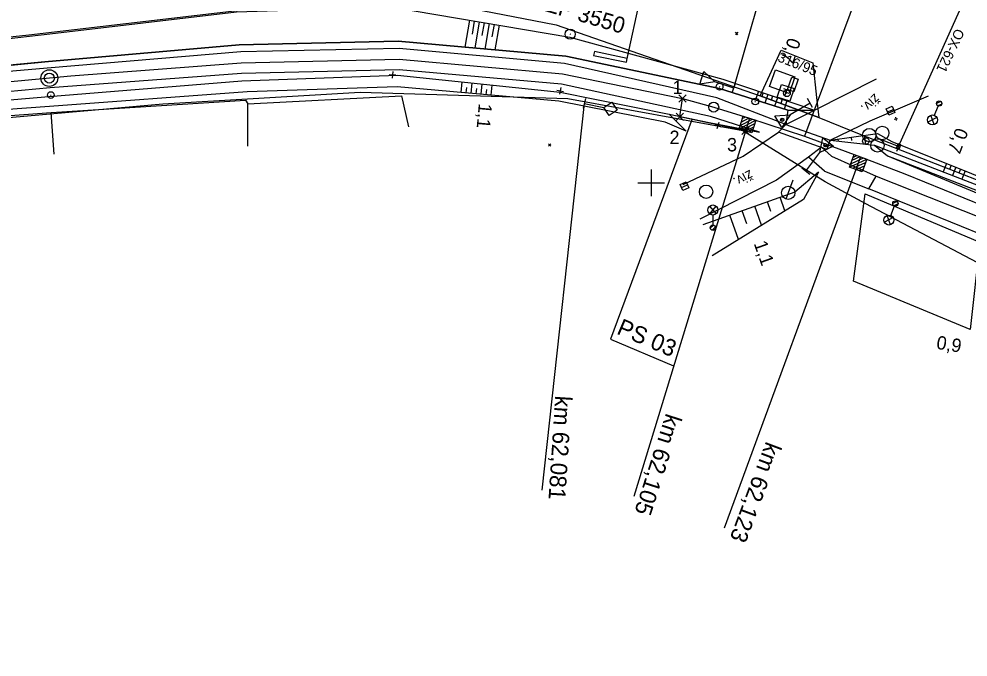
# Model space of a CAD drawing. Extents: x -805636 to -804553, y -1165340 to -1164656.
# Drawn here: x -805494.5 to -805352.6, y -1164970.9 to -1164875.5 of the extents above; entities that cross this region are included whole.
import ezdxf

# ---------------------------------------------------------------- set-up
doc = ezdxf.new("R2010")
doc.units = 0
for name, color, linetype in [('0381KM061-064P - Vrstva 1', 7, 'Continuous'), ('0381KM061-064P - Vrstva 12', 7, 'Continuous'), ('0381KM061-064P - Vrstva 16', 7, 'Continuous'), ('0381KM061-064P - Vrstva 17', 7, 'Continuous'), ('0381KM061-064P - Vrstva 23', 7, 'Continuous'), ('0381KM061-064P - Vrstva 25', 7, 'Continuous'), ('0381KM061-064P - Vrstva 27', 7, 'Continuous'), ('0381KM061-064P - Vrstva 3', 7, 'Continuous'), ('0381KM061-064P - Vrstva 33', 7, 'Continuous'), ('0381KM061-064P - Vrstva 4', 7, 'Continuous'), ('0381KM061-064P - Vrstva 43', 7, 'Continuous'), ('0381KM061-064P - Vrstva 48', 7, 'Continuous'), ('0381KM061-064P - Vrstva 49', 7, 'Continuous'), ('0381KM061-064P - Vrstva 51', 7, 'Continuous'), ('0381KM061-064P - Vrstva 55', 7, 'Continuous'), ('0381KM061-064P - Vrstva 57', 7, 'Continuous'), ('0381KM061-064P - Vrstva 7', 7, 'Continuous'), ('0381KM061-064P - Vrstva 8', 7, 'Continuous'), ('0381KM061-064P - Vrstva 9', 7, 'Continuous'), ('Default', 7, 'Continuous'), ('hran DP - hran DP', 7, 'Continuous'), ('krizky_1000 - Vrstva 1', 7, 'Continuous'), ('PSR_C2_3_Lomove_body_Lenora - Vrstva 60', 7, 'Continuous'), ('PSR_C2_3_trasa_Lenora - Kabelová trasa', 7, 'Continuous'), ('SOPS', 7, 'Continuous'), ('vyt_sit - stávající', 7, 'Continuous')]:
    doc.layers.add(name, color=color, linetype=linetype)

msp = doc.modelspace()

# ---------------------------------------------------------------- linework, layer by layer
at = {"layer": '0381KM061-064P - Vrstva 1'}
msp.add_line((-805413.27, -1164883.66), (-805395.31, -1164887.39), dxfattribs=at)
for points in [[(-805621.7, -1164896.48), (-805615.58, -1164895.98), (-805590.01, -1164893.62), (-805528.48, -1164887.9), (-805486.76, -1164883.98), (-805461.3, -1164882.03), (-805437.69, -1164881.51), (-805413.27, -1164883.66)], [(-805395.31, -1164887.39), (-805390.66, -1164888.66), (-805385.3, -1164890.3), (-805377.11, -1164893.01), (-805368.7, -1164896.09), (-805362.07, -1164898.64)], [(-805362.07, -1164898.64), (-805347.39, -1164904.64), (-805344.65, -1164905.78)]]:
    msp.add_lwpolyline(points, dxfattribs=at)
at = {"layer": '0381KM061-064P - Vrstva 12'}
for p, q in [((-805363.35, -1164894.76), (-805363.11, -1164894.15)), ((-805362.92, -1164894.93), (-805362.69, -1164894.32)), ((-805362.92, -1164894.93), (-805362.69, -1164894.32))]:
    msp.add_line(p, q, dxfattribs=at)
for points in [[(-805363.35, -1164894.76), (-805363.35, -1164894.76), (-805363.11, -1164894.15), (-805363.11, -1164894.15), (-805362.69, -1164894.32), (-805362.69, -1164894.32), (-805363.11, -1164894.15)], [(-805363.35, -1164894.76), (-805362.92, -1164894.93), (-805362.92, -1164894.93), (-805363.35, -1164894.76)]]:
    msp.add_lwpolyline(points, dxfattribs=at)
at = {"layer": '0381KM061-064P - Vrstva 16'}
msp.add_lwpolyline([(-805366.38, -1164898.98), (-805348.12, -1164906.22), (-805348.61, -1164907.57), (-805349.09, -1164908.36), (-805367.46, -1164900.88), (-805366.38, -1164898.98)], dxfattribs=at)
at = {"layer": '0381KM061-064P - Vrstva 17'}
for p, q in [((-805460.29, -1164894.52), (-805460.29, -1164888.19)), ((-805489.25, -1164895.68), (-805489.69, -1164889.49))]:
    msp.add_line(p, q, dxfattribs=at)
for points in [[(-805536.86, -1164897.86), (-805537.37, -1164893.17), (-805513.54, -1164891.19), (-805489.69, -1164889.49), (-805460.65, -1164887.61), (-805460.29, -1164888.19), (-805437.32, -1164886.99), (-805436.25, -1164891.59)], [(-805369.75, -1164914.7), (-805368.04, -1164901.63), (-805350.89, -1164908.84), (-805352.32, -1164921.91), (-805369.75, -1164914.7)]]:
    msp.add_lwpolyline(points, dxfattribs=at)
at = {"layer": '0381KM061-064P - Vrstva 23'}
msp.add_lwpolyline([(-805382.32, -1164885.58), (-805381.44, -1164883.1), (-805378.52, -1164884.13), (-805379.4, -1164886.61)], close=True, dxfattribs=at)
at = {"layer": '0381KM061-064P - Vrstva 25'}
for p, q in [((-805356.71, -1164887.82), (-805357.36, -1164888.1)), ((-805357.68, -1164889.88), (-805357.11, -1164888.5)), ((-805356.57, -1164888.2), (-805357.18, -1164888.45)), ((-805357.3, -1164890.23), (-805358.64, -1164890.89)), ((-805357.72, -1164891.28), (-805358.22, -1164889.87)), ((-805363.25, -1164902.78), (-805363.9, -1164903.06)), ((-805363.11, -1164903.15), (-805363.72, -1164903.42)), ((-805391.28, -1164903.49), (-805390.28, -1164904.6)), ((-805391.26, -1164904.62), (-805390.28, -1164903.5)), ((-805390.78, -1164904.8), (-805390.78, -1164906.3)), ((-805364.22, -1164906.25), (-805364.74, -1164904.85)), ((-805364.2, -1164904.85), (-805363.65, -1164903.45)), ((-805363.82, -1164905.19), (-805365.15, -1164905.87)), ((-805391.17, -1164906.78), (-805390.7, -1164906.31)), ((-805390.9, -1164907.08), (-805390.4, -1164906.58))]:
    msp.add_line(p, q, dxfattribs=at)
msp.add_lwpolyline([(-805378.69, -1164886.38), (-805379.63, -1164886.05), (-805378.96, -1164884.16), (-805378.02, -1164884.5), (-805378.69, -1164886.38)], dxfattribs=at)
for centre, radius in [((-805356.96, -1164888.12), 0.4), ((-805356.96, -1164888.12), 0.4), ((-805357.96, -1164890.58), 0.749), ((-805390.78, -1164904.05), 0.749), ((-805363.5, -1164903.08), 0.4), ((-805363.5, -1164903.08), 0.4), ((-805364.47, -1164905.55), 0.749), ((-805390.78, -1164906.7), 0.4), ((-805390.78, -1164906.7), 0.4)]:
    msp.add_circle(centre, radius, dxfattribs=at)
at = {"layer": '0381KM061-064P - Vrstva 27'}
for p, q in [((-805384.49, -1164887.81), (-805384.39, -1164887.81)), ((-805379.67, -1164886.61), (-805379.76, -1164886.58)), ((-805367.98, -1164893.73), (-805367.88, -1164893.73))]:
    msp.add_line(p, q, dxfattribs=at)
for centre in [(-805379.71, -1164886.59), (-805384.44, -1164887.81), (-805367.93, -1164893.73)]:
    msp.add_circle(centre, 0.5, dxfattribs=at)
at = {"layer": '0381KM061-064P - Vrstva 3'}
for p, q in [((-805385.3, -1164890.3), (-805402.6, -1164946.88)), ((-805386.87, -1164891.9), (-805384.35, -1164890.6)), ((-805386.7, -1164891.39), (-805384.86, -1164890.44)), ((-805386.54, -1164890.89), (-805385.36, -1164890.28)), ((-805386.38, -1164890.38), (-805385.87, -1164890.12)), ((-805386.36, -1164892.06), (-805384.51, -1164891.11)), ((-805385.86, -1164892.22), (-805384.67, -1164891.61)), ((-805385.35, -1164892.38), (-805384.84, -1164892.12)), ((-805368.7, -1164896.09), (-805389.1, -1164951.65)), ((-805370.16, -1164897.12), (-805368.26, -1164896.26)), ((-805369.97, -1164896.62), (-805368.76, -1164896.07)), ((-805369.78, -1164896.13), (-805369.26, -1164895.89)), ((-805370.34, -1164897.62), (-805367.77, -1164896.44)), ((-805369.85, -1164897.8), (-805367.95, -1164896.94)), ((-805369.35, -1164897.99), (-805368.14, -1164897.44)), ((-805368.85, -1164898.17), (-805368.33, -1164897.93))]:
    msp.add_line(p, q, dxfattribs=at)
for points in [[(-805386.26, -1164889.99), (-805384.35, -1164890.6), (-805384.96, -1164892.51), (-805386.87, -1164891.9)], [(-805369.64, -1164895.74), (-805367.77, -1164896.44), (-805368.47, -1164898.32), (-805370.34, -1164897.62)]]:
    msp.add_lwpolyline(points, close=True, dxfattribs=at)
at = {"layer": '0381KM061-064P - Vrstva 33'}
for p, q in [((-805380.22, -1164885.9), (-805379.27, -1164886.21)), ((-805379.74, -1164886.05), (-805380.06, -1164887))]:
    msp.add_line(p, q, dxfattribs=at)
msp.add_lwpolyline([(-805380.53, -1164885.26), (-805378.63, -1164885.89), (-805379.26, -1164887.79), (-805381.16, -1164887.16), (-805380.53, -1164885.26)], dxfattribs=at)
at = {"layer": '0381KM061-064P - Vrstva 4'}
for p, q in [((-805355.47, -1164835.15), (-805377.11, -1164893.01)), ((-805461.56, -1164879.34), (-805437.82, -1164878.81)), ((-805437.82, -1164878.81), (-805412.78, -1164881.05)), ((-805490.63, -1164881.9), (-805461.56, -1164879.34)), ((-805461.35, -1164880.4), (-805490.28, -1164882.82)), ((-805437.68, -1164879.9), (-805461.35, -1164880.4)), ((-805412.96, -1164882.16), (-805437.68, -1164879.9)), ((-805528.63, -1164885.47), (-805490.63, -1164881.9)), ((-805390.18, -1164887.25), (-805412.96, -1164882.16)), ((-805412.78, -1164881.05), (-805389.79, -1164885.89)), ((-805490.28, -1164882.82), (-805528.62, -1164886.23)), ((-805379.87, -1164891.27), (-805390.18, -1164887.25)), ((-805375.87, -1164888.73), (-805376.65, -1164887.39)), ((-805380.17, -1164890.61), (-805380.65, -1164890.49)), ((-805374.21, -1164894.39), (-805373.72, -1164894.33)), ((-805377.5, -1164897.74), (-805376.27, -1164898.69))]:
    msp.add_line(p, q, dxfattribs=at)
for points in [[(-805383.82, -1164892.41), (-805391.14, -1164890.05), (-805413.4, -1164885.24), (-805437.69, -1164883.08), (-805461.24, -1164883.62), (-805489.81, -1164885.79), (-805528.46, -1164889.37), (-805589.94, -1164895), (-805615.48, -1164897.55), (-805622.38, -1164898.08)], [(-805622.83, -1164899.13), (-805615.58, -1164898.49), (-805589.92, -1164896.02), (-805528.49, -1164890.34), (-805490.03, -1164887.06), (-805461.18, -1164884.75), (-805437.91, -1164883.87), (-805413.61, -1164886.43), (-805397.33, -1164889.69), (-805391.36, -1164890.97), (-805383.82, -1164892.41)], [(-805389.79, -1164885.89), (-805379.56, -1164889.14), (-805379.87, -1164891.27)], [(-805376.26, -1164888.06), (-805379.25, -1164889.83), (-805380.48, -1164891.7), (-805381.5, -1164889.98), (-805379.25, -1164889.83)], [(-805380.99, -1164892.42), (-805379.87, -1164891.27), (-805373.25, -1164893.62), (-805373.77, -1164894.98), (-805380.99, -1164892.42)], [(-805376.89, -1164898.22), (-805374.77, -1164895.46), (-805374.33, -1164893.27), (-805372.74, -1164894.48), (-805374.77, -1164895.46)], [(-805364.7, -1164895.97), (-805343.19, -1164904.86), (-805317.03, -1164915.68), (-805296.75, -1164924.42), (-805284.83, -1164929.56), (-805254.7, -1164942.26), (-805226.16, -1164954.55), (-805203.52, -1164964.18), (-805187.57, -1164970.92)], [(-805364.7, -1164895.97), (-805342.91, -1164904.36), (-805316.81, -1164915.12), (-805296.46, -1164924.13), (-805284.52, -1164929.13), (-805254.45, -1164941.83), (-805225.92, -1164953.93), (-805203.38, -1164963.47), (-805187.4, -1164970.45)]]:
    msp.add_lwpolyline(points, dxfattribs=at)
for centre in [(-805380.41, -1164890.55), (-805373.96, -1164894.36)]:
    msp.add_circle(centre, 0.248, dxfattribs=at)
at = {"layer": '0381KM061-064P - Vrstva 43'}
msp.add_line((-805378.82, -1164899.61), (-805379.87, -1164902.41), dxfattribs=at)
for points in [[(-805364.7, -1164889.39), (-805364.89, -1164888.94), (-805363.98, -1164888.54), (-805363.58, -1164889.46), (-805364.5, -1164889.85), (-805364.7, -1164889.39), (-805363.78, -1164889)], [(-805395.46, -1164900.7), (-805395.68, -1164900.25), (-805394.78, -1164899.82), (-805394.35, -1164900.72), (-805395.25, -1164901.15), (-805395.46, -1164900.7), (-805394.56, -1164900.27)]]:
    msp.add_lwpolyline(points, dxfattribs=at)
for centre, radius in [((-805391.79, -1164901.31), 1), ((-805379.52, -1164901.48), 0.996)]:
    msp.add_circle(centre, radius, dxfattribs=at)
at = {"layer": '0381KM061-064P - Vrstva 48'}
for p, q in [((-805427.18, -1164875.65), (-805427.86, -1164879.7)), ((-805426.44, -1164875.78), (-805426.78, -1164877.77)), ((-805425.7, -1164875.9), (-805426.36, -1164879.83)), ((-805424.96, -1164876.03), (-805425.29, -1164877.96)), ((-805424.22, -1164876.15), (-805424.86, -1164879.97)), ((-805423.48, -1164876.28), (-805423.8, -1164878.16)), ((-805422.74, -1164876.4), (-805423.37, -1164880.1)), ((-805428.38, -1164886.47), (-805428.24, -1164884.89)), ((-805427.64, -1164886.54), (-805427.57, -1164885.75)), ((-805426.89, -1164886.61), (-805426.75, -1164885.04)), ((-805426.14, -1164886.67), (-805426.07, -1164885.9)), ((-805425.39, -1164886.74), (-805425.26, -1164885.2)), ((-805424.65, -1164886.8), (-805424.58, -1164886.04)), ((-805423.9, -1164886.87), (-805423.77, -1164885.36)), ((-805383.98, -1164886.28), (-805384.43, -1164887.59)), ((-805383.27, -1164886.53), (-805383.49, -1164887.17)), ((-805382.56, -1164886.77), (-805383, -1164888.05)), ((-805381.85, -1164887.01), (-805382.07, -1164887.64)), ((-805381.14, -1164887.25), (-805381.57, -1164888.5)), ((-805380.43, -1164887.49), (-805380.64, -1164888.11)), ((-805379.72, -1164887.73), (-805380.14, -1164888.96)), ((-805372.01, -1164893.76), (-805372.05, -1164893.46)), ((-805370, -1164893.66), (-805370.07, -1164893.18)), ((-805367.91, -1164894.21), (-805368.1, -1164892.9)), ((-805355.86, -1164897.08), (-805356.37, -1164898.34)), ((-805355.16, -1164897.36), (-805355.42, -1164897.99)), ((-805354.47, -1164897.64), (-805354.97, -1164898.88)), ((-805353.77, -1164897.92), (-805354.02, -1164898.54)), ((-805353.08, -1164898.2), (-805353.57, -1164899.43)), ((-805382.1, -1164904.28), (-805382.62, -1164902.82)), ((-805380.01, -1164904.18), (-805380.73, -1164902.15)), ((-805386.96, -1164908.48), (-805388.26, -1164904.83)), ((-805385.69, -1164906.1), (-805386.38, -1164904.16)), ((-805383.49, -1164906.33), (-805384.5, -1164903.49))]:
    msp.add_line(p, q, dxfattribs=at)
at = {"layer": '0381KM061-064P - Vrstva 49'}
for p, q in [((-805387.06, -1164877.83), (-805387.41, -1164877.47)), ((-805387.06, -1164877.47), (-805387.41, -1164877.83)), ((-805363.68, -1164890.45), (-805363.19, -1164890.34)), ((-805363.49, -1164890.15), (-805363.38, -1164890.64)), ((-805366.17, -1164892.62), (-805364.02, -1164893.8)), ((-805414.99, -1164894.49), (-805415.34, -1164894.14)), ((-805414.99, -1164894.14), (-805415.34, -1164894.49)), ((-805366.61, -1164894.35), (-805364.49, -1164895.2))]:
    msp.add_line(p, q, dxfattribs=at)
for points in [[(-805619.35, -1164890.95), (-805615.91, -1164890.53), (-805590.56, -1164886.39), (-805529.03, -1164882.21), (-805489.9, -1164877.68), (-805461.98, -1164874.39), (-805438.96, -1164873.66), (-805412.14, -1164878.2), (-805389.29, -1164884.48), (-805375.6, -1164889.14)], [(-805379.56, -1164889.14), (-805389.79, -1164885.89), (-805412.78, -1164881.05), (-805437.82, -1164878.81), (-805461.56, -1164879.34), (-805490.63, -1164881.9), (-805528.63, -1164885.47), (-805589.69, -1164890.91), (-805616.18, -1164893.18), (-805620.48, -1164893.61)], [(-805622.83, -1164899.13), (-805615.58, -1164898.49), (-805589.92, -1164896.02), (-805528.49, -1164890.34), (-805490.03, -1164887.06), (-805461.18, -1164884.75), (-805437.91, -1164883.87), (-805413.61, -1164886.43), (-805397.33, -1164889.69), (-805394.79, -1164892.28)], [(-805394.79, -1164892.28), (-805397.93, -1164890.9), (-805413.8, -1164887.77), (-805437.96, -1164885.62), (-805460.38, -1164886.37), (-805489.93, -1164888.57), (-805513.35, -1164890.24), (-805537.4, -1164892.44), (-805590.64, -1164897.22), (-805615.62, -1164899.61), (-805623.38, -1164900.43)], [(-805379.56, -1164889.14), (-805375.6, -1164889.14)], [(-805373.25, -1164893.62), (-805366.17, -1164892.62)], [(-805373.25, -1164893.62), (-805366.61, -1164894.35)], [(-805366.61, -1164894.35), (-805364.7, -1164895.97), (-805342.91, -1164904.36), (-805316.81, -1164915.12), (-805296.46, -1164924.13)], [(-805364.02, -1164893.8), (-805346.07, -1164901.02), (-805315.87, -1164912.66), (-805295.19, -1164922.01)], [(-805364.49, -1164895.2), (-805347.1, -1164901.93), (-805316.44, -1164914.01), (-805295.94, -1164922.85)], [(-805374.97, -1164898.41), (-805378.55, -1164901.37), (-805392.29, -1164906.26)], [(-805374.97, -1164898.41), (-805377.24, -1164902.47), (-805390.88, -1164910.9)]]:
    msp.add_lwpolyline(points, dxfattribs=at)
at = {"layer": '0381KM061-064P - Vrstva 51'}
for p, q in [((-805380.99, -1164892.42), (-805379.87, -1164891.27)), ((-805373.06, -1164895.99), (-805366.38, -1164898.98)), ((-805374.09, -1164898.25), (-805367.46, -1164900.88))]:
    msp.add_line(p, q, dxfattribs=at)
for points in [[(-805379.87, -1164891.27), (-805375.6, -1164889.14), (-805366.34, -1164884.42)], [(-805373.25, -1164893.62), (-805367.29, -1164890.73), (-805358.55, -1164886.97)], [(-805395.22, -1164900.25), (-805386.26, -1164896), (-805380.99, -1164892.42)], [(-805374.56, -1164894.67), (-805376.47, -1164896.14), (-805381.29, -1164899.6), (-805392.72, -1164905.44)], [(-805374.56, -1164894.67), (-805373.77, -1164894.98), (-805373.25, -1164893.62)], [(-805373.06, -1164895.99), (-805374.56, -1164894.67)], [(-805374.09, -1164898.25), (-805376.47, -1164896.14)]]:
    msp.add_lwpolyline(points, dxfattribs=at)
at = {"layer": '0381KM061-064P - Vrstva 55'}
msp.add_lwpolyline([(-805383.69, -1164886.97), (-805380.55, -1164880.12), (-805375.86, -1164882.04), (-805375.28, -1164887.22), (-805374.94, -1164890.22)], close=True, dxfattribs=at)
at = {"layer": '0381KM061-064P - Vrstva 7'}
for p, q in [((-805438.62, -1164883.31), (-805438.7, -1164884.31)), ((-805439.16, -1164883.76), (-805438.16, -1164883.85)), ((-805414.09, -1164886.11), (-805413.11, -1164886.31)), ((-805413.5, -1164885.72), (-805413.7, -1164886.7)), ((-805389.82, -1164885.59), (-805389.72, -1164885.62)), ((-805489.78, -1164886.86), (-805489.68, -1164886.85)), ((-805390.5, -1164891.3), (-805389.54, -1164891.6)), ((-805389.87, -1164890.97), (-805390.17, -1164891.93))]:
    msp.add_line(p, q, dxfattribs=at)
for centre, radius in [((-805489.96, -1164884.32), 1.25), ((-805489.96, -1164884.32), 0.752), ((-805489.73, -1164886.85), 0.5), ((-805389.77, -1164885.6), 0.5), ((-805390.66, -1164888.66), 0.75)]:
    msp.add_circle(centre, radius, dxfattribs=at)
at = {"layer": '0381KM061-064P - Vrstva 8'}
for p, q in [((-805387.65, -1164885.82), (-805372.19, -1164831.77)), ((-805363.02, -1164894.54), (-805338.8, -1164840.62)), ((-805392.11, -1164883.34), (-805390.51, -1164884.9)), ((-805387.88, -1164886.53), (-805387.42, -1164885.1)), ((-805409.84, -1164887.37), (-805410.15, -1164888.84)), ((-805410, -1164888.1), (-805416.33, -1164945.95)), ((-805363.02, -1164894.54), (-805365.82, -1164893.46)), ((-805363.28, -1164895.24), (-805362.75, -1164893.84))]:
    msp.add_line(p, q, dxfattribs=at)
for points in [[(-805387.65, -1164885.82), (-805390.51, -1164884.9), (-805392.72, -1164885.24), (-805392.11, -1164883.34), (-805390.51, -1164884.9)], [(-805410, -1164888.1), (-805407.06, -1164888.71), (-805405.88, -1164887.94), (-805405.1, -1164889.12), (-805406.28, -1164889.9), (-805407.06, -1164888.71)]]:
    msp.add_lwpolyline(points, dxfattribs=at)
for centre in [(-805367.4, -1164892.85), (-805365.46, -1164892.53), (-805366.18, -1164894.4)]:
    msp.add_circle(centre, 1, dxfattribs=at)
at = {"layer": '0381KM061-064P - Vrstva 9'}
for p, q in [((-805403.65, -1164881.66), (-805391.9, -1164827.49)), ((-805408.48, -1164880.35), (-805408.6, -1164880.94)), ((-805403.58, -1164881.37), (-805408.48, -1164880.35)), ((-805408.6, -1164880.94), (-805403.71, -1164881.96)), ((-805403.71, -1164881.96), (-805403.58, -1164881.37)), ((-805403.58, -1164881.37), (-805403.46, -1164880.78))]:
    msp.add_line(p, q, dxfattribs=at)
at = {"layer": 'hran DP - hran DP'}
for p, q in [((-805433.01, -1164872.7), (-805414.19, -1164876.33)), ((-805493.02, -1164877.83), (-805461.06, -1164874.13)), ((-805414.19, -1164876.33), (-805383.69, -1164886.97)), ((-805559.43, -1164885.25), (-805493.02, -1164877.83)), ((-805443.5, -1164886.48), (-805472.98, -1164888.24)), ((-805412.47, -1164887.44), (-805443.5, -1164886.48)), ((-805386.3, -1164892.2), (-805412.47, -1164887.44)), ((-805383.69, -1164886.97), (-805374.94, -1164890.22)), ((-805472.98, -1164888.24), (-805537.37, -1164893.92)), ((-805374.94, -1164890.22), (-805370.14, -1164892.15)), ((-805373.99, -1164899.86), (-805386.3, -1164892.2)), ((-805370.14, -1164892.15), (-805367.78, -1164893.1)), ((-805367.78, -1164893.1), (-805249.75, -1164939.24)), ((-805367.9, -1164903.11), (-805373.99, -1164899.86)), ((-805346.65, -1164914.36), (-805367.9, -1164903.11))]:
    msp.add_line(p, q, dxfattribs=at)
at = {"layer": 'krizky_1000 - Vrstva 1'}
for points in [[(-805400, -1164898), (-805400, -1164902)], [(-805402, -1164900), (-805398, -1164900)]]:
    msp.add_lwpolyline(points, dxfattribs=at)
at = {"layer": 'PSR_C2_3_Lomove_body_Lenora - Vrstva 60'}
for p, q in [((-805395.86, -1164887.94), (-805394.76, -1164886.84)), ((-805394.76, -1164887.94), (-805395.86, -1164886.84)), ((-805396.25, -1164890.67), (-805395.15, -1164889.57)), ((-805395.15, -1164890.67), (-805396.25, -1164889.57)), ((-805386.46, -1164892.75), (-805385.36, -1164891.65)), ((-805385.36, -1164892.75), (-805386.46, -1164891.65))]:
    msp.add_line(p, q, dxfattribs=at)
at = {"layer": 'PSR_C2_3_trasa_Lenora - Kabelová trasa'}
msp.add_lwpolyline([(-805385.91, -1164892.2), (-805395.7, -1164890.12), (-805395.31, -1164887.39)], dxfattribs=at)
msp.add_lwpolyline([(-805385.91, -1164892.2), (-805395.7, -1164890.12), (-805395.31, -1164887.39)], dxfattribs=at)
at = {"layer": 'SOPS'}
for p, q in [((-805393.86, -1164890.4), (-805406.1, -1164923.36)), ((-805406.1, -1164923.36), (-805396.68, -1164927.37))]:
    msp.add_line(p, q, dxfattribs=at)
at = {"layer": 'vyt_sit - stávající'}
msp.add_line((-805412.14, -1164877.72), (-805412.06, -1164877.77), dxfattribs=at)
msp.add_circle((-805412.1, -1164877.75), 0.756, dxfattribs=at)

# ---------------------------------------------------------------- texts
at = {"layer": '0381KM061-064P - Vrstva 3'}
for s, rotation, p in [('km 62,105', 252.2096, (-805397.76, -1164934.35)), ('km 62,123', 249.4698, (-805382.81, -1164938.56))]:
    msp.add_text(s, height=2.5, rotation=rotation, dxfattribs=at).set_placement(p)
at = {"layer": '0381KM061-064P - Vrstva 48'}
for s, rotation, p in [('0,7', 251.1992, (-805379.49, -1164878.14)), ('1,1', 264.9104, (-805425.76, -1164888.06)), ('0,7', 248.8398, (-805354.41, -1164891.6)), ('1,1', 289.5856, (-805384.7, -1164909.05)), ('0,9', 350.7698, (-805357.47, -1164924.8))]:
    msp.add_text(s, height=2, rotation=rotation, dxfattribs=at).set_placement(p)
at = {"layer": '0381KM061-064P - Vrstva 51'}
for rotation, p in [(223.2619, (-805366.61, -1164886.55)), (207.0403, (-805385.24, -1164897.99))]:
    msp.add_text('živ.', height=1.5, rotation=rotation, dxfattribs=at).set_placement(p)
at = {"layer": '0381KM061-064P - Vrstva 57'}
msp.add_text('316/95', height=1.5, rotation=338.4457, dxfattribs=at).set_placement((-805381.22, -1164881.77))
at = {"layer": '0381KM061-064P - Vrstva 8'}
for s, height, rotation, p in [('OX-621', 1.5, 244.7151, (-805354.47, -1164876.78)), ('km 62,081', 2.5, 266.2962, (-805414.34, -1164931.77))]:
    msp.add_text(s, height=height, rotation=rotation, dxfattribs=at).set_placement(p)
at = {"layer": 'Default'}
for s, p in [('1', (-805396.82, -1164886.7)), ('2', (-805397.26, -1164894.18)), ('3', (-805388.66, -1164895.28))]:
    msp.add_text(s, height=2, dxfattribs=at).set_placement(p)
at = {"layer": 'SOPS'}
msp.add_text('PS 03', height=2.5, rotation=336.9516, dxfattribs=at).set_placement((-805405.3, -1164922.52))
at = {"layer": 'vyt_sit - stávající'}
msp.add_text('ŽP 3550', height=2.4, rotation=343.5611, dxfattribs=at).set_placement((-805415.96, -1164874.28))

doc.saveas('drawing.dxf')
